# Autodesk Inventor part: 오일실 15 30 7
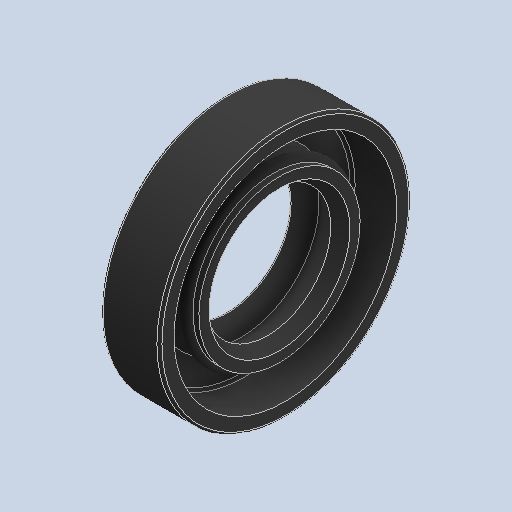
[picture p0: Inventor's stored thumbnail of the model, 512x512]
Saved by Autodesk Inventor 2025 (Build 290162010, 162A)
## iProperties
Created: 2024-07
Part Number: 오일실 15 30 7
Material: 고무
Description: 오일-실
Document SubType Name: Modeling
Designer: 학생
Density: 0.93 g/cm^3
Appearance: 기본값
Author: jhkim
Sending System: Autodesk Inventor 2025
Preprocessor: ST-DEVELOPER v20
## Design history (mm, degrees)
feature "Solid1"
node "솔리드1"
